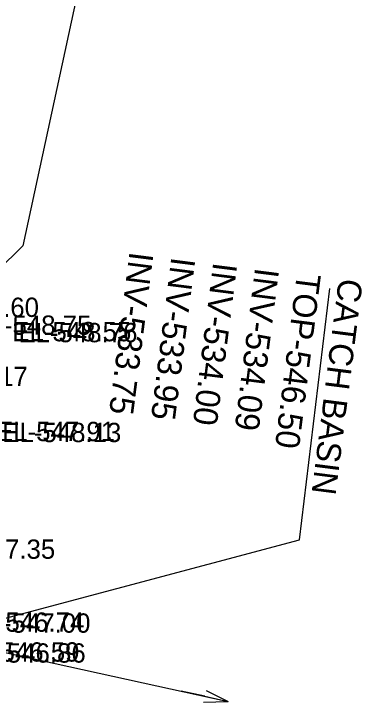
# Model space of a CAD drawing. Extents: x 1724534 to 1727318, y 657156 to 660047.
# Drawn here: x 1725701.5 to 1725773.8, y 659714.5 to 659857.1 of the extents above; entities that cross this region are included whole.
import ezdxf

# ---------------------------------------------------------------- set-up
doc = ezdxf.new("R2010")
doc.units = 0
for name, color, linetype in [('SURVEY - CENTERLINE - Preliminary Text', 7, 'Continuous'), ('SURVEY - DRAINAGE - Storm Sewer', 7, 'Continuous'), ('SURVEY - DRAINAGE - Storm Sewer Text', 7, 'Continuous'), ('SURVEY - DTM - Breaklines - Points - Elevations', 7, 'Continuous'), ('SURVEY - TRAFFIC CONTROL - Pavement Marking - Points - Elevations', 7, 'Continuous'), ('SURVEY - TRANSPORTATION - Features - Points - Elevations', 7, 'Continuous'), ('SURVEY - TRANSPORTATION - Roads - Points - Elevations', 7, 'Continuous')]:
    doc.layers.add(name, color=color, linetype=linetype)

msp = doc.modelspace()

# ---------------------------------------------------------------- linework, layer by layer
at = {"layer": 'SURVEY - CENTERLINE - Preliminary Text'}
for p in [(1725746.28, 660007.42), (1725658.7, 659765.22)]:
    msp.add_line(p, (1725703.39, 659809.01), dxfattribs=at)
at = {"layer": 'SURVEY - DRAINAGE - Storm Sewer'}
for p, q in [((1725684.98, 659727.99), (1725746.01, 659714.65)), ((1725741.13, 659715.72), (1725736.24, 659716.79)), ((1725741.4, 659716.94), (1725746.01, 659714.65)), ((1725740.86, 659714.5), (1725746.01, 659714.65)), ((1725741.13, 659715.72), (1725746.01, 659714.65)), ((1725741.13, 659715.72), (1725746.01, 659714.65))]:
    msp.add_line(p, q, dxfattribs=at)
at = {"layer": 'SURVEY - DRAINAGE - Storm Sewer Text'}
msp.add_lwpolyline([(1725684.98, 659727.99), (1725760.77, 659748.13), (1725767.07, 659800.19)], dxfattribs=at)

# ---------------------------------------------------------------- texts
for s, p in [('INV-533.75', (1725725.56, 659807.96)), ('INV-533.95', (1725734.24, 659806.85)), ('INV-534.00', (1725742.92, 659805.75)), ('INV-534.09', (1725751.6, 659804.64)), ('TOP-546.50', (1725760.28, 659803.54)), ('CATCH BASIN', (1725768.96, 659802.44))]:
    msp.add_text(s, height=5, rotation=262.7515, dxfattribs=at).set_placement(p)
at = {"layer": 'SURVEY - DTM - Breaklines - Points - Elevations'}
for s, p in [('EL-548.76', (1725702.5, 659789.07)), ('EL-548.13', (1725699.15, 659768.38)), ('EL-547.00', (1725692.76, 659728.9)), ('EL-546.86', (1725691.77, 659722.7))]:
    msp.add_text(s, height=4, dxfattribs=at).set_placement(p)
at = {"layer": 'SURVEY - TRAFFIC CONTROL - Pavement Marking - Points - Elevations'}
for s, p in [('EL-548.60', (1725682.08, 659794.31)), ('EL-548.17', (1725679.76, 659779.99))]:
    msp.add_text(s, height=4, dxfattribs=at).set_placement(p)
at = {"layer": 'SURVEY - TRANSPORTATION - Features - Points - Elevations'}
for s, p in [('EL-548.55', (1725701.22, 659789.27)), ('EL-547.91', (1725697.86, 659768.59)), ('EL-546.74', (1725691.48, 659729.1)), ('EL-546.59', (1725690.48, 659722.91))]:
    msp.add_text(s, height=4, dxfattribs=at).set_placement(p)
at = {"layer": 'SURVEY - TRANSPORTATION - Roads - Points - Elevations'}
for s, p in [('EL-548.75', (1725692.95, 659790.61)), ('EL-547.35', (1725685.45, 659744.21))]:
    msp.add_text(s, height=4, dxfattribs=at).set_placement(p)

doc.saveas('drawing.dxf')
